// Mitsubishi GX Works2 project: 68用中断程序精确计时   PLC: FX3U/FX3UC

PROGRAM MAIN
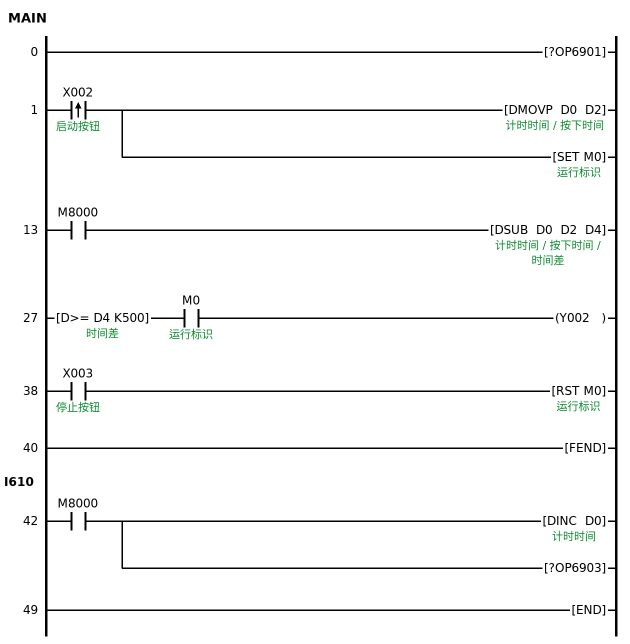
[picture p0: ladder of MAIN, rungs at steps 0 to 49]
0     ?OP6901
1     LDP     X002  ; 启动按钮
      DMOVP   D0 D2  ; 计时时间 / 按下时间
      SET     M0  ; 运行标识
13    LD      M8000
      DSUB    D0 D2 D4  ; 时间差
27    LDD>=   D4 K500  ; 时间差
      AND     M0  ; 运行标识
      OUT     Y002
38    LD      X003  ; 停止按钮
      RST     M0  ; 运行标识
40    FEND
      I610
42    LD      M8000
      DINC    D0
      ?OP6903
49    END
END_PROGRAM

// device comments not shown above
I610  ; 10ms中断一次
